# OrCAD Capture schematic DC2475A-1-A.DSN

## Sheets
1 PAGE2: size Custom
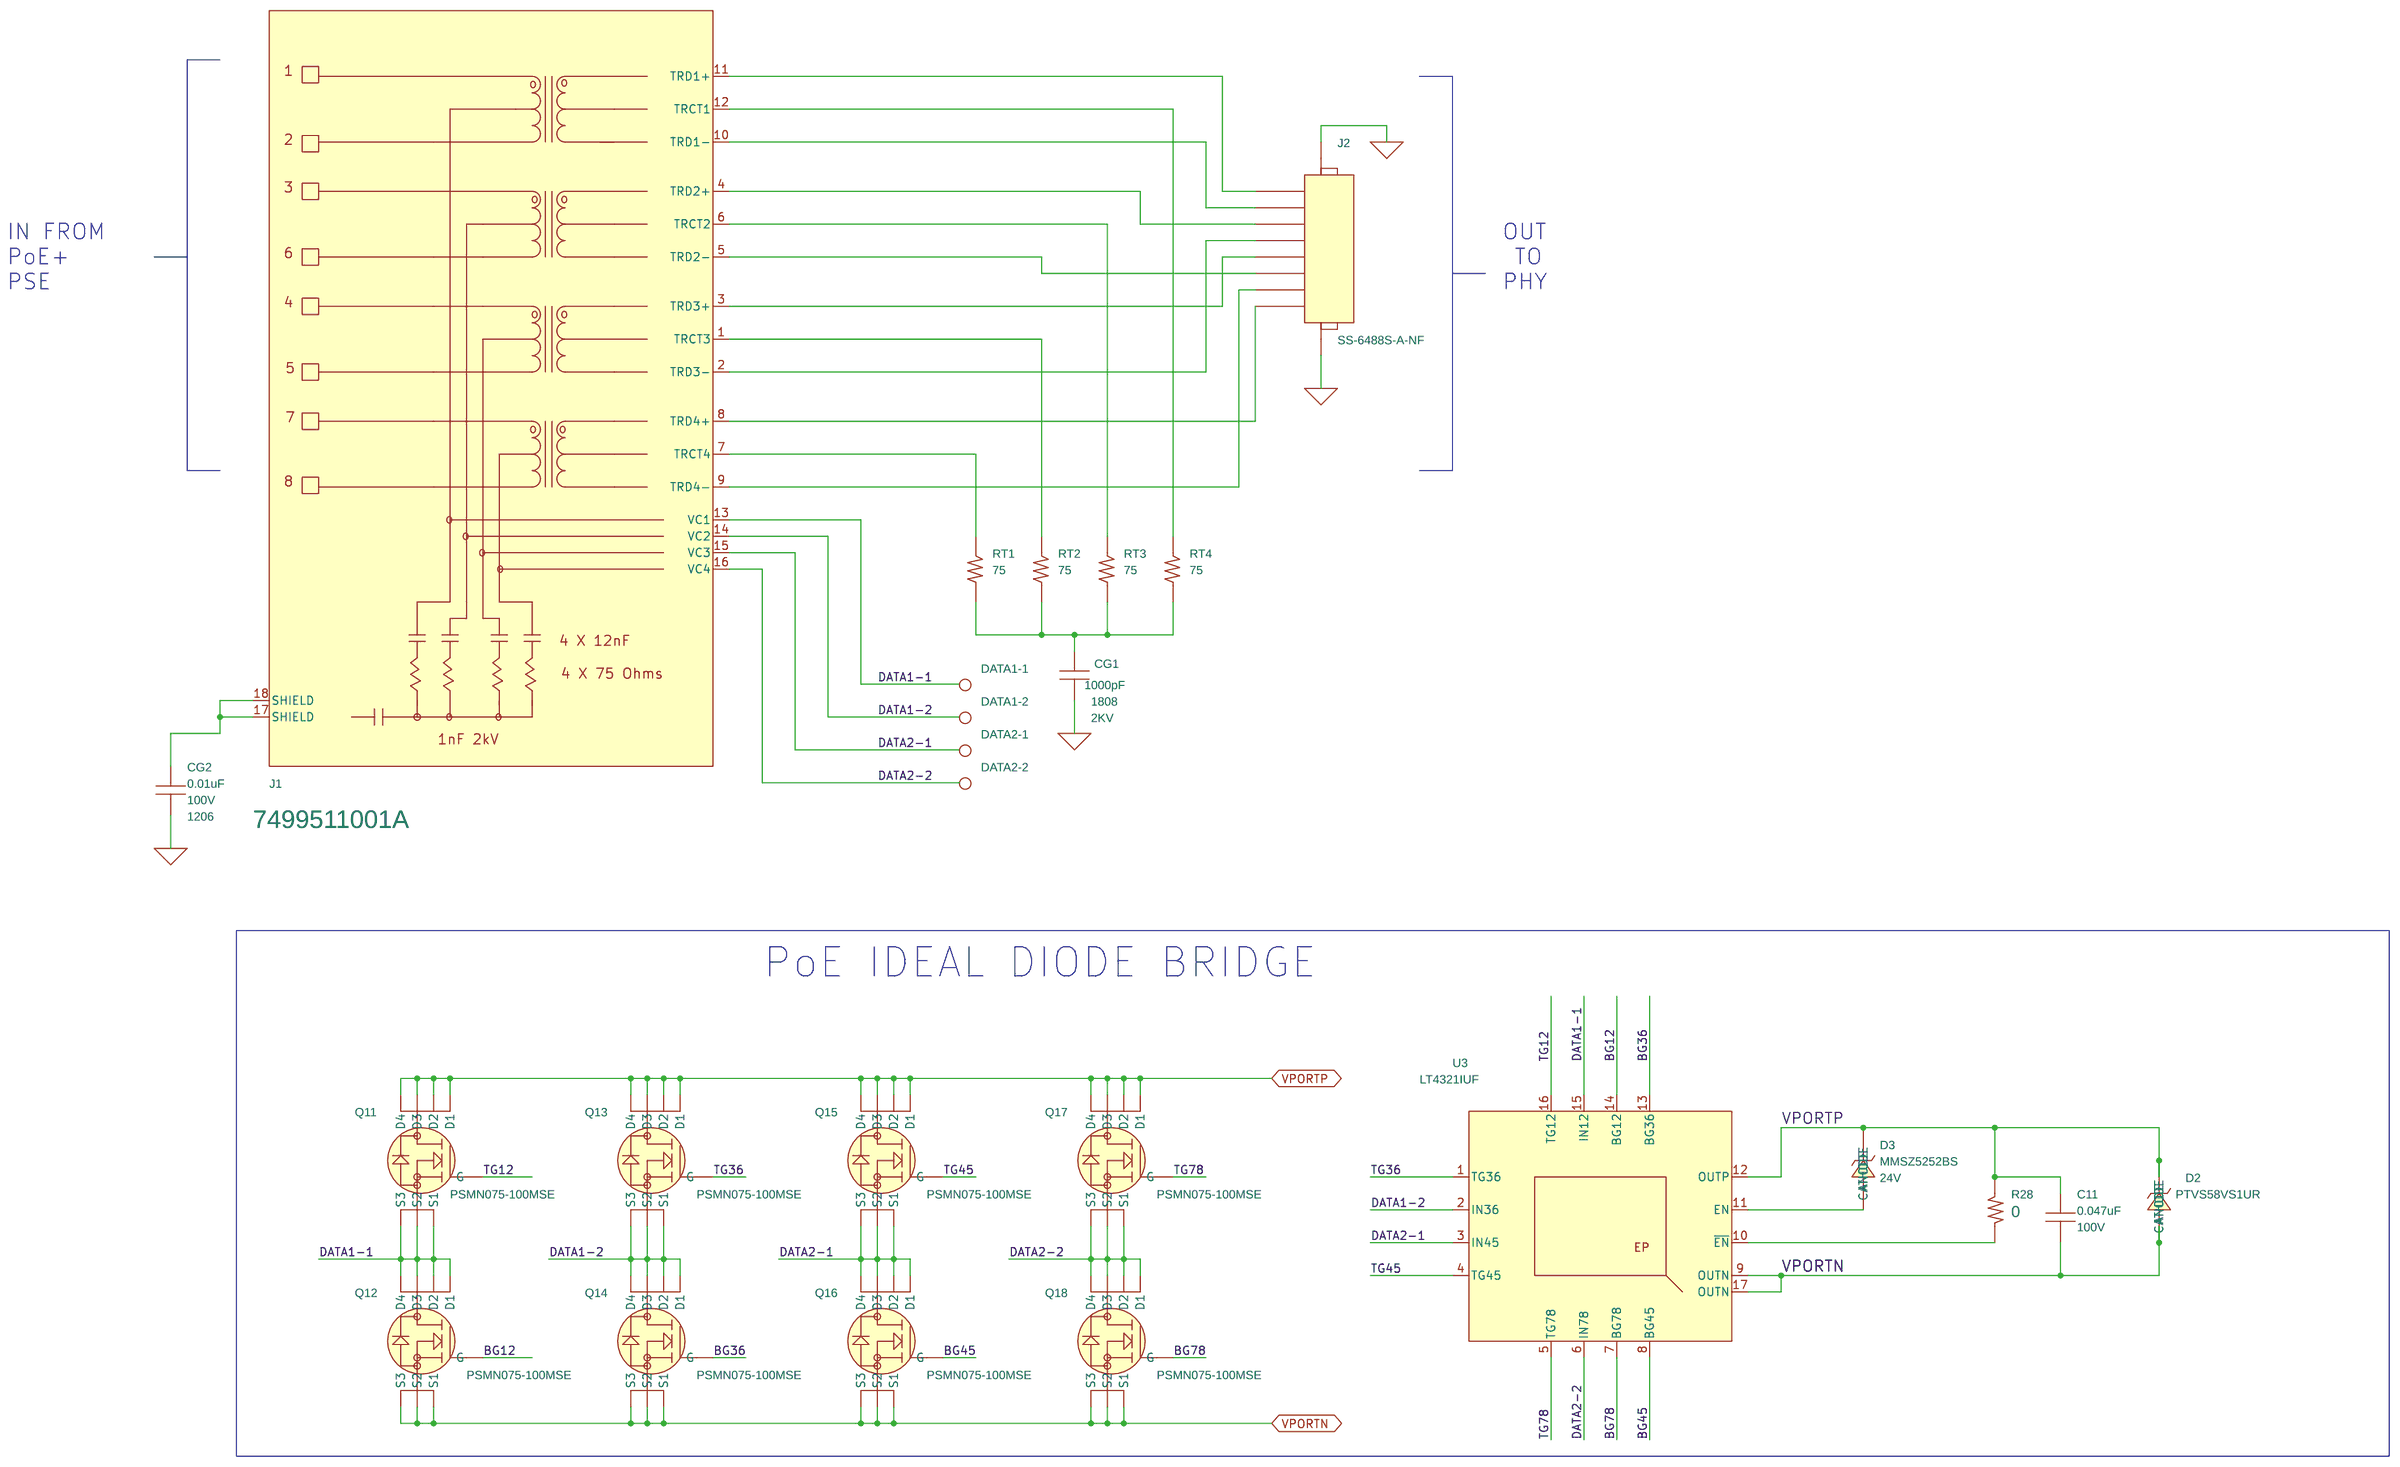
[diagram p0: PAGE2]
2 PAGE1: size Custom
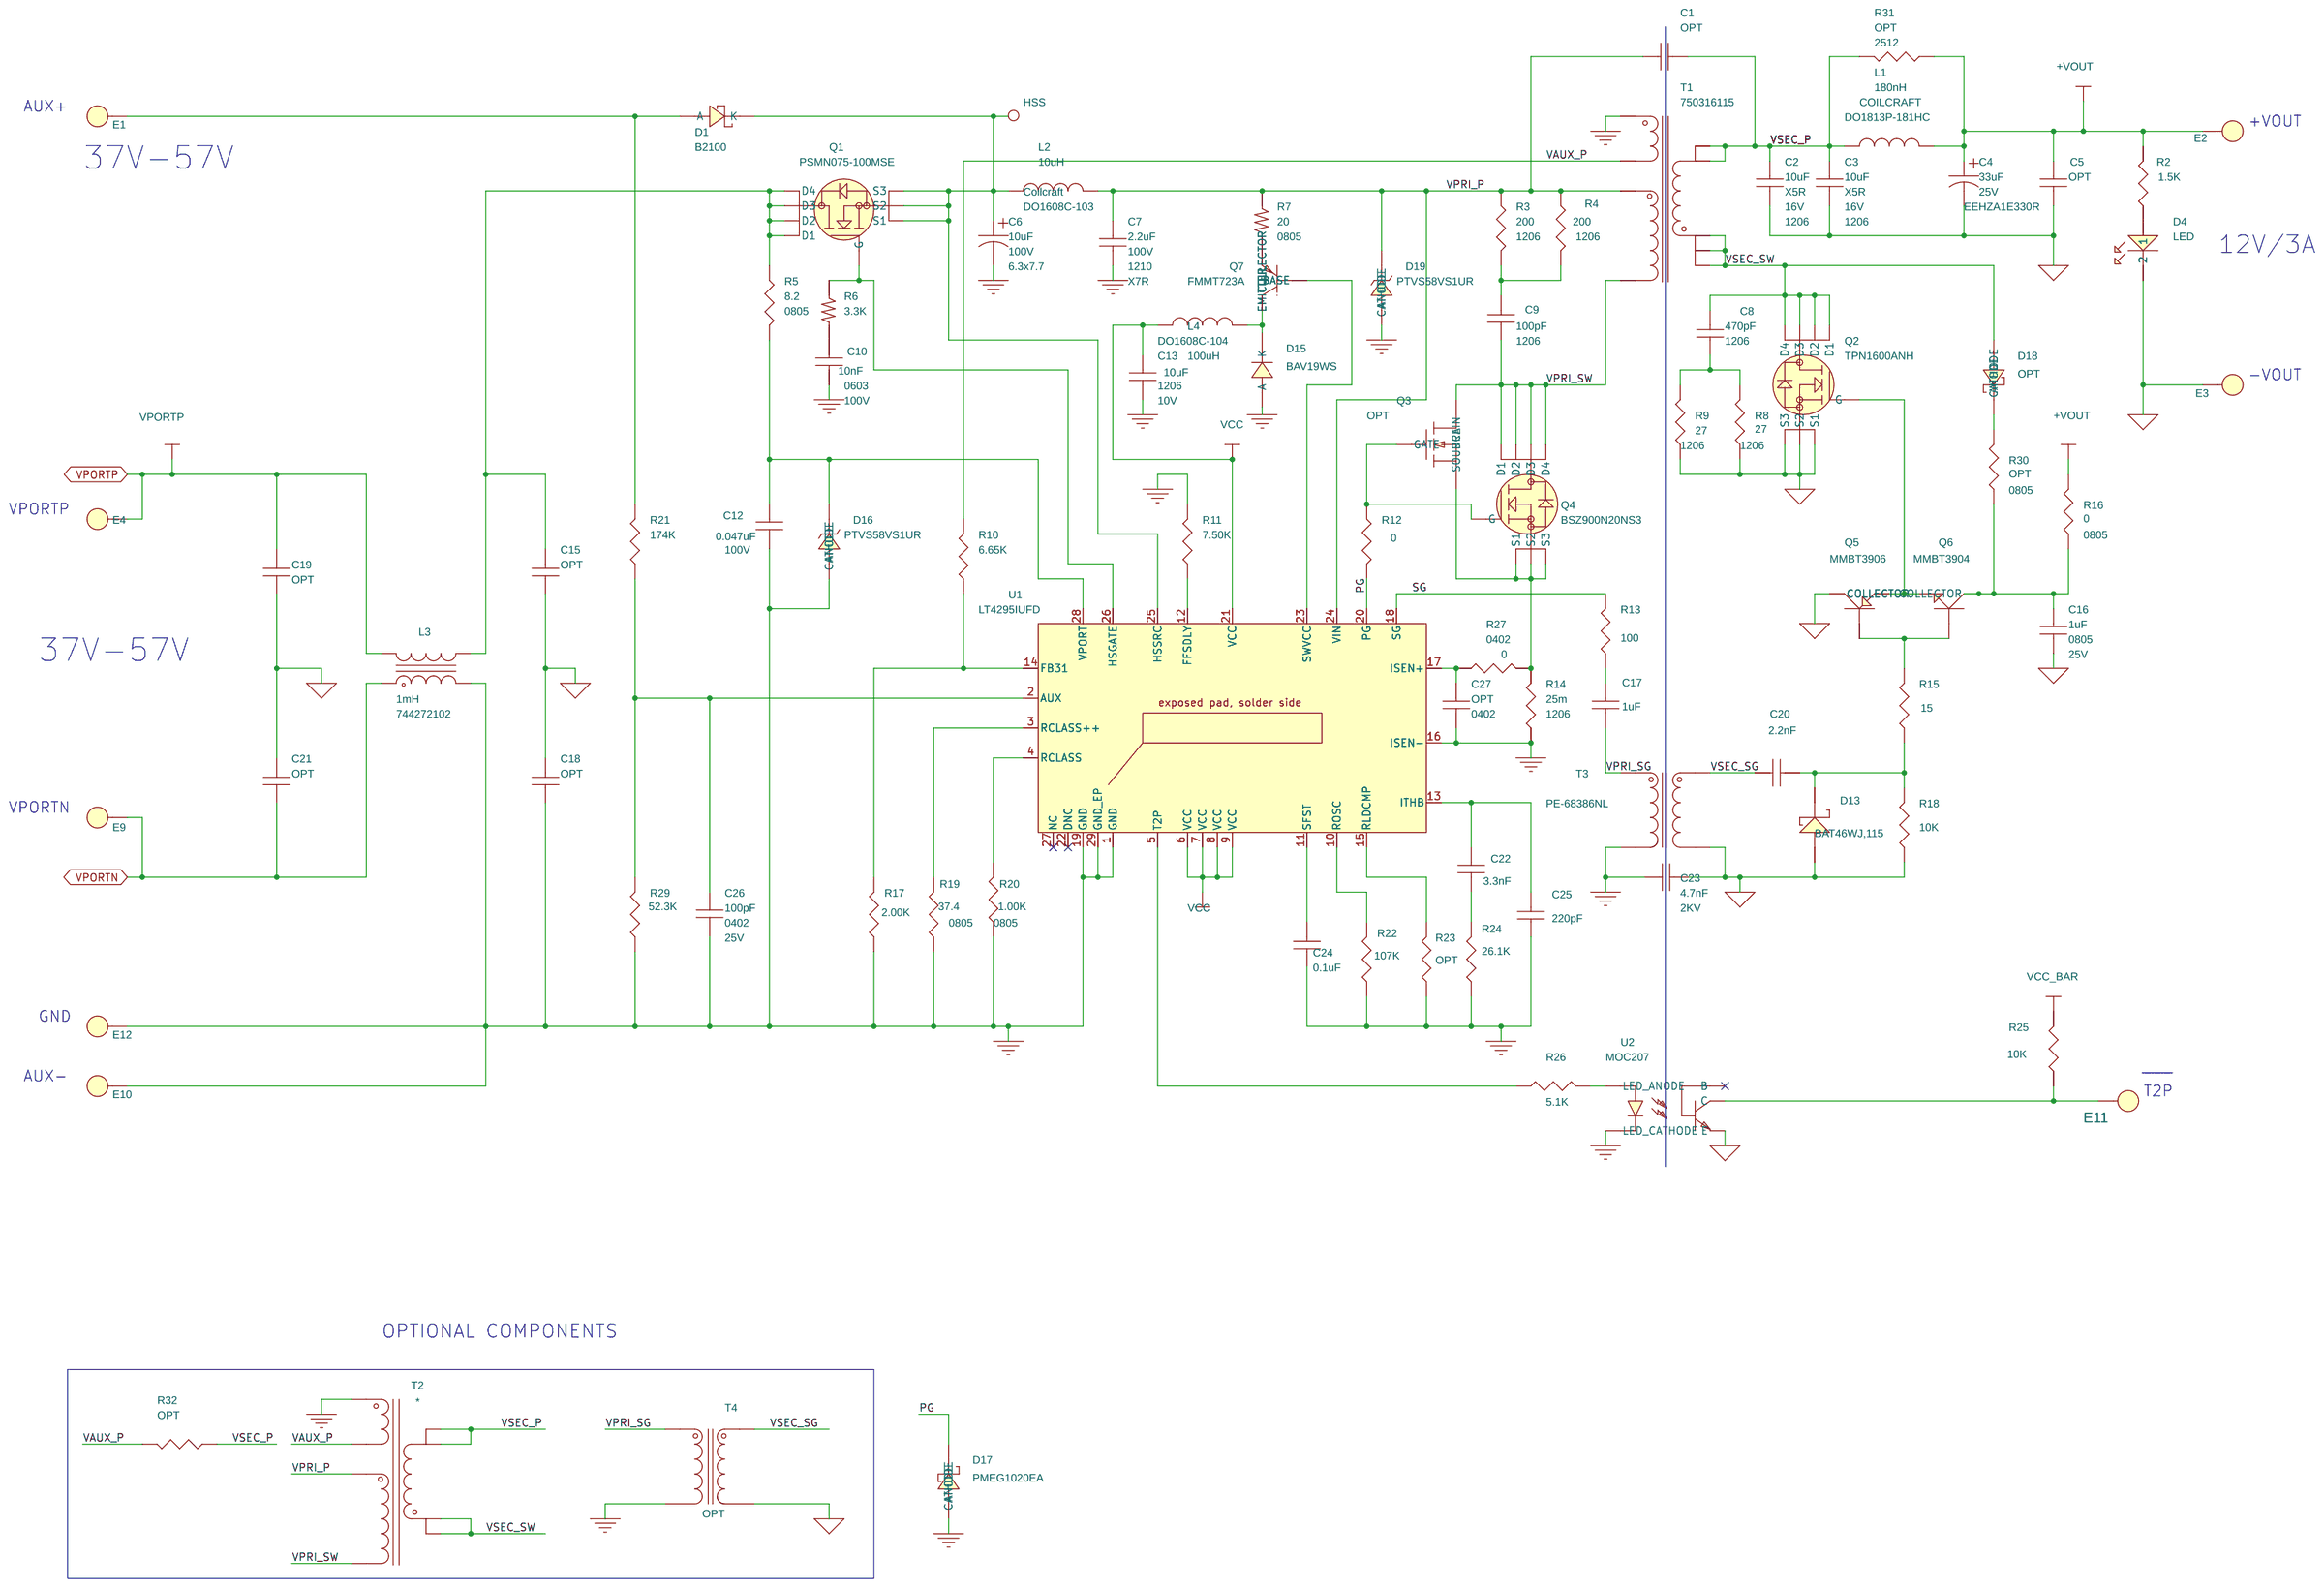
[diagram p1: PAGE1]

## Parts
sheet PAGE1
C1  OPT  [1812]
C2  10uF  [1206]
C3  10uF  [1206]
C4  33uF  [C-SANYO-B6-5.0X5.9]
C5  OPT  [1210]
C6  10uF  [SANYO\6.3X7.7]
C7  2.2uF  [1210]
C8  470pF  [1206]
C9  100pF  [1206]
C10  10nF  [0603]
C12  0.047uF  [0805]
C13  10uF  [1206]
C15  OPT  [1812]
C16  1uF  [0805]
C17  1uF  [0603]
C18  OPT  [1812]
C19  OPT  [1812]
C20  2.2nF  [0603]
C21  OPT  [1812]
C22  3.3nF  [0603]
C23  4.7nF  [1812]
C24  0.1uF  [0603]
C25  220pF  [0603]
C26  100pF  [0402]
C27  OPT  [0402]
D1  B2100  [SMB-DIODE]
D4  LED  [LED-ROHM-SML-010]
D13  BAT46WJ,115  [SOD323]
D15  BAV19WS
D16  PTVS58VS1UR  [SOD123]
D17  PMEG1020EA  [SOD323]
D18  OPT  [SOD323]
D19  PTVS58VS1UR  [SOD123]
E1  PAD150-094  [PAD150-094]
E2  PAD150-094  [PAD150-094]
E3  PAD150-094  [PAD150-094]
E4  PAD150-094  [PAD150-094]
E9  PAD150-094  [PAD150-094]
E10  PAD150-094  [PAD150-094]
E11  PAD150-094  [PAD150-094]
E12  PAD150-094  [PAD150-094]
HSS  E-SMT-060  [SMTP]
L1  180nH  [DO1813P-HC]
L2  10uH  [IND-COILCRAFT-DO1608C]
L3  1mH  [IND-WURTH-744272332]
L4  100uH  [IND-COILCRAFT-DO1608C]
Q1  PSMN075-100MSE  [POWERPAK1212]
Q2  TPN1600ANH  [POWER33]
Q3  OPT  [SOT23]
Q4  BSZ900N20NS3  [POWER33]
Q5  MMBT3906  [SOT23]
Q6  MMBT3904  [SOT23]
Q7  FMMT723A  [SOT23]
R2  1.5K  [0805]
R3  200  [1206]
R4  200  [1206]
R5  8.2  [0805]
R6  3.3K  [0603]
R7  20  [0805]
R8  27  [1206]
R9  27  [1206]
R10  6.65K  [0603]
R11  7.50K  [0603]
R12  0  [0603]
R13  100  [0603]
R14  25m  [1206]
R15  15  [0603]
R16  0  [0805]
R17  2.00K  [0603]
R18  10K  [0603]
R19  37.4  [0805]
R20  1.00K  [0805]
R21  174K  [0603]
R22  107K  [0603]
R23  OPT  [0603]
R24  26.1K  [0603]
R25  10K  [0603]
R26  5.1K  [0603]
R27  0  [0402]
R29  52.3K  [0603]
R30  OPT  [0805]
R31  OPT  [2512]
R32  OPT  [1812]
T1  750316115  [TRANS-PULSE-EP13]
T2  *  [TRANS-WURTH-EP7]
T3  PE-68386NL  [TRANSFORMER/PULSE/PE-68386]
T4  OPT  [TRANS-EPCOS-T5476]
U1  LT4295IUFD  [QFN28UFD-4X5]
U2  MOC207  [SO8NB]
sheet PAGE2
C11  0.047uF  [0603]
CG1  1000pF  [1808]
CG2  0.01uF  [1206]
D2  PTVS58VS1UR  [SOD123]
D3  MMSZ5252BS  [SOD323]
DATA1-1  E-SMT-060  [SMTP]
DATA1-2  E-SMT-060  [SMTP]
DATA2-1  E-SMT-060  [SMTP]
DATA2-2  E-SMT-060  [SMTP]
J1  7499511001A  [TRANS-WURTH-7499511001]
J2  SS-6488S-A-NF  [CON-SS7188]
Q11  PSMN075-100MSE  [POWERPAK1212]
Q12  PSMN075-100MSE  [POWERPAK1212]
Q13  PSMN075-100MSE  [POWERPAK1212]
Q14  PSMN075-100MSE  [POWERPAK1212]
Q15  PSMN075-100MSE  [POWERPAK1212]
Q16  PSMN075-100MSE  [POWERPAK1212]
Q17  PSMN075-100MSE  [POWERPAK1212]
Q18  PSMN075-100MSE  [POWERPAK1212]
R28  0  [0603]
RT1  75  [0603]
RT2  75  [0603]
RT3  75  [0603]
RT4  75  [0603]
U3  LT4321IUF  [QFN16UF-4X4]

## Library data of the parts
C1 = CAP-NP: 1st Part: Cap; 2nd Part Type: Cer; 5th Voltage: 2kV
C2 C3 = CAP-NP: 1st Part: CAP; 2nd Part Type: Cer; 3rd Tempco: X5R; 5th Voltage: 16V; 6th Tolerance: 10%; 8th Mfr: Murata; 9th Part Number: GRM31CR61C106KA88
C4 = CAP: 2nd Part Type: Elec; 5th Voltage: 25V; 6th Tolerance: 20%; 7th Size: 5.0X5.8; 8th Mfr: PANASONIC; 9th Part Number: EEHZA1E330R
C5 = CAP-NP: 1st Part: CAP; 2nd Part Type: Cer; 3rd Tempco: X7U; 5th Voltage: 6.3V; 6th Tolerance: 10%
C6 = CAP: 2nd Part Type: Elec; 5th Voltage: 100V; 6th Tolerance: 10%; 7th Size: 6.3x7.7; 8th Mfr: SunCon; 9th Part Number: 100CE10BS
C7 = CAP-NP: 1st Part: CAP; 2nd Part Type: Cer; 3rd Tempco: X7R; 5th Voltage: 100V; 6th Tolerance: 10%; 8th Mfr: Murata; 9th Part Number: GRM32ER72A225KA35
C8 = CAP-NP: 1st Part: Cap; 2nd Part Type: Cer; 3rd Tempco: U2J; 5th Voltage: 630V; 6th Tolerance: 5%; 8th Mfr: Murata; 9th Part Number: GRM31A7U2J471JW31D
C9 = CAP-NP: 1st Part: Cap; 2nd Part Type: Cer; 3rd Tempco: U2J; 5th Voltage: 630V; 6th Tolerance: 5%; 8th Mfr: Murata
C10 = CAP-NP: 1st Part: Cap; 2nd Part Type: Cer; 3rd Tempco: X7R; 5th Voltage: 100V; 6th Tolerance: 20%; 8th Mfr: TBD
C12 = CAP-NP: 1st Part: Cap; 2nd Part Type: Cer; 3rd Tempco: X7R; 5th Voltage: 100V; 6th Tolerance: 10%; 8th Mfr: TBD
C13 = CAP-NP: 1st Part: Cap; 2nd Part Type: Cer; 3rd Tempco: X7R; 5th Voltage: 10V; 6th Tolerance: 10%; 8th Mfr: Murata; 9th Part Number: GRM31CR71A106KA01L
C15 C18 C19 C21 = CAP-NP: 1st Part: Cap; 2nd Part Type: Cer; 3rd Tempco: X5R; 5th Voltage: 2KV; 6th Tolerance: 20%
C16 C22 = CAP-NP: 1st Part: Cap; 2nd Part Type: Cer; 3rd Tempco: X7R; 5th Voltage: 25V; 6th Tolerance: 10%; 8th Mfr: TBD
C17 = CAP-NP: 1st Part: Cap; 2nd Part Type: Cer; 3rd Tempco: X7R; 5th Voltage: 25V; 6th Tolerance: 10%; 8th Mfr: Murata; 9th Part Number: GRM188R71E105KA12
C20 = CAP-NP: 1st Part: Cap; 2nd Part Type: Cer; 3rd Tempco: X7R; 5th Voltage: 25V; 6th Tolerance: 10%; 8th Mfr: Murata; 9th Part Number: GRM188R71E222KA01
C23 = CAP-NP: 1st Part: Cap; 2nd Part Type: Cer; 3rd Tempco: X7R; 5th Voltage: 2KV; 8th Mfr: Murata; 9th Part Number: GR443DR73D472KW01L
C24 = CAP-NP: 1st Part: Cap; 2nd Part Type: Cer; 3rd Tempco: X7R; 5th Voltage: 25V; 6th Tolerance: 20%; 8th Mfr: TBD
C25 C26 = CAP-NP: 1st Part: Cap; 2nd Part Type: Cer; 3rd Tempco: X7R; 5th Voltage: 25V; 6th Tolerance: 10%; 8th Mfr: TBD; 9th Part Number: TBD
C27 = CAP-NP: 1st Part: Cap; 2nd Part Type: Cer; 3rd Tempco: X7R; 5th Voltage: 6.3V; 6th Tolerance: 10%; 8th Mfr: TBD
D1 = DIODE_SCHOTTKY21_0: 1st Part: DIODE; 2nd Part Type: SCHOTTKY; 5th Voltage: 100; 7th Size: SMB; 8th Mfr: DIODE INC
D4 = LED_0: 1st Part: DIODE; 8th Mfr: ROHM; 9th Part Number: SML-010FTT86L
D13 = DIODE-SCHOTTKY_0: 1st Part: DIODE; 2nd Part Type: Schottky; 5th Voltage: 100; 8th Mfr: NXP
D15 = DIODE_4: 1st Part: Diode; 2nd Part Type: DIODE; 5th Voltage: 120V; 7th Size: SOD323; 8th Mfr: DIODE INC
D16 = DIODE_ZENER_0: 1st Part: DIODE; 2nd Part Type: TVS; 5th Voltage: 60; 8th Mfr: NXP
D17 = DIODE_SCHOTTKY_0: 1st Part: Diode; 2nd Part Type: Schottky; 5th Voltage: 10V; 8th Mfr: NXP
D18 = DIODE_SCHOTTKY_0: 1st Part: Diode; 2nd Part Type: DIODE INC; 5th Voltage: 30V; 8th Mfr: DIODE INC
D2 D19 = DIODE_ZENER_0: 1st Part: DIODE; 2nd Part Type: TVS; 5th Voltage: 58; 8th Mfr: NXP
E1 E4 E9 E10 E12 = E: TURRETS; 1st Part: TP; 2nd Part Type: TURRET; 7th Size: 0.094"; 8th Mfr: MILL-MAX; 9th Part Number: 2501-2-00-80-00-00-07-0; Part Number: MILLMAX 2501-2
E2 E3 E11 = E: 1st Part: TP; 2nd Part Type: TURRET; 7th Size: 0.094"; 8th Mfr: MILL-MAX; 9th Part Number: 2501-2-00-80-00-00-07-0
DATA1-1 DATA1-2 DATA2-1 DATA2-2 HSS = E-SMT-060: 1st Part: CONN; 2nd Part Type: TP
L1 = IND: 8th Mfr: COILCRAFT; 9th Part Number: DO1813P-181HC
L2 = IND: 8th Mfr: Coilcraft; 9th Part Number: DO1608C-103
L3 = IND_0: 1st Part: IND; 2nd Part Type: CMC; 8th Mfr: Wurth; 9th Part Number: 744272102
L4 = IND: 8th Mfr: Coilcraft; 9th Part Number: DO1608C-104
Q1 Q11-Q18 = MOSFET_N-DIODE-A-SO8: 1st Part: MOSFET; 2nd Part Type: N-CH; 5th Voltage: 100; 7th Size: LFPAK33; 8th Mfr: NXP
Q2 = MOSFET_N-DIODE-A-SO8: 1st Part: MOSFET; 2nd Part Type: N-CH; 5th Voltage: 100V; 7th Size: POWER-33; 8th Mfr: TOSHIBA
Q3 = FDN8601_1: 1st Part: MOSFET; 2nd Part Type: N-CH; 5th Voltage: 100
Q4 = MOSFET_N-DIODE-A-SO8: 1st Part: MOSFET; 2nd Part Type: N-CH; 5th Voltage: 150; 7th Size: PG-TDSON-8; 8th Mfr: INFINEON
Q5 = PNP_0: 1st Part: TRANSISTOR; 2nd Part Type: PNP; 5th Voltage: 40; 8th Mfr: FAIRCHILD
Q6 = NPN_0: 1st Part: TRANSISTOR; 2nd Part Type: NPN; 5th Voltage: 40; 8th Mfr: FAIRCHILD
Q7 = MMBT5401L: 1st Part: Tran; 2nd Part Type: PNP; 5th Voltage: 100V; 8th Mfr: DIODES INC; 9th Part Number: FMMT723
R2-R5 R8 R9 R12 R13 R15 R16 R18 R22 R25-R27 = CR18-274JM: 1st Part: Res; 2nd Part Type: Chip; 6th Tolerance: 5%; 8th Mfr: TBD
R6 R7 = R: 1st Part: Res; 2nd Part Type: Chip; 6th Tolerance: 5%; 8th Mfr: TBD
R10 R11 R14 R17 R20 R24 R32 = CR18-274JM: 1st Part: Res; 2nd Part Type: Chip; 6th Tolerance: 1%; 8th Mfr: TBD
R19 = CR18-274JM: 1st Part: Res; 2nd Part Type: Chip; 6th Tolerance: 1%; 8th Mfr: OPT
R21 R29 = CR18-274JM: 1st Part: Res; 2nd Part Type: Chip; 6th Tolerance: 1%; 8th Mfr: TBD; 9th Part Number: TBD
R23 R30 = CR18-274JM: 1st Part: Res; 2nd Part Type: Chip; 6th Tolerance: 5%
R31 = CR18-274JM: 1st Part: Res; 2nd Part Type: Chip; 4th Value: 0; 6th Tolerance: 5%; 8th Mfr: TBD
T1 = TRANS-VP3_1: 1st Part: XFMR; 2nd Part Type: Flyback Tran; 8th Mfr: WURTH
T2 = TRANS-VP3_2: 1st Part: XFMR; 2nd Part Type: Flyback Tran; 8th Mfr: WURTH; 9th Part Number: TBD
T3 = TRANS-PA0297_2: 1st Part: XFMR; 2nd Part Type: SMD GATE DRIVE; 4TH PART FIELD: PULSE,; 8th Mfr: PULSE
T4 = TRANS-PA0297_1: 1st Part: XFMR; 2nd Part Type: SMD GATE DRIVE; 4TH PART FIELD: PULSE,; 8th Mfr: EPCOS; 9th Part Number: T5476
U1 = LT4276_3: 1st Part: IC; 2nd Part Type: PD & Switcher Controller; 7th Size: QFN28; 8th Mfr: Linear Tech
U2 = MOC207: 1st Part: Opto; 5th Voltage: 70V; 7th Size: SO8; 8th Mfr: FAIRCHILD; 9th Part Number: MOC207M
C11 CG2 = CAP-NP: 1st Part: CAP; 2nd Part Type: Cer; 3rd Tempco: X7R; 5th Voltage: 100V; 6th Tolerance: 20%; 8th Mfr: TBD; Voltage Rating: 100V
CG1 = CAP-NP: 1st Part: Cap; 2nd Part Type: Cer; 3rd Tempco: X7R; 5th Voltage: 2KV; 6th Tolerance: 10%; 8th Mfr: Murata; 9th Part Number: GR442QR73D102KW01L
D3 = DIODE_ZENER_0: 1st Part: DIODE; 2nd Part Type: Zener; 5th Voltage: 24V; 8th Mfr: Diodes Inc; 9th Part Number: MMSZ5256BS
J1 = TRNSFMR_165P_8: 1st Part: CONN; 2nd Part Type: Integrated Jack; 8th Mfr: Wurth
J2 = 8_HEADER_1: 1st Part: CONN; 2nd Part Type: RJ45 Jack; 8th Mfr: Stewart Connector
R28 = R: 1st Part: Res; 2nd Part Type: Chip; 6th Tolerance: 5%; 8th Mfr: TBD; Tolerance: 5%
RT1-RT4 = R: 1st Part: Res; 2nd Part Type: Chip; 6th Tolerance: 5%; 8th Mfr: AAC; 9th Part Number: CR16-750JM
U3 = LT4321_QFN_1: 1st Part: IC; 2nd Part Type: PoE Ideal Bridge Controller; 7th Size: QFN16; 8th Mfr: Linear Tech; 9th Part Number: LT4321

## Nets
GND_POWER: C6.2 C7.2 C10.2 C12.2 C13.2 C18.1 C23.1 C24.1 C25.1 C26.2 C27.2 D15.2(A) D16.2(ANODE) D17.2(ANODE) D19.2(ANODE) E10.1(A) E12.1(A) L3.3 R11.2 R14.2 R17.1 R19.1 R20.1 R22.1 R23.1 R24.1 R29.1 T1.2 T2.2 T3.3 T4.3 U1.1(GND) U1.16(ISEN-) U1.19(GND) U1.29(GND_EP) U2.2(LED_CATHODE)
VCC: C13.1 L4.1 U1.6(VCC) U1.7(VCC) U1.8(VCC) U1.9(VCC) U1.21(VCC)
+VOUT: C4.1 C5.1 E2.1(A) L1.2 R2.2 R16.2 R25.2 R31.1
BG12: Q12.4(G) U3.14(BG12)
BG36: Q14.4(G) U3.13(BG36)
BG45: Q16.4(G) U3.8(BG45)
BG78: Q18.4(G) U3.7(BG78)
DATA1-1: DATA1-1.1 J1.13(VC1) Q11.1(S1) Q11.2(S2) Q11.3(S3) Q12.5(D1) Q12.6(D2) Q12.7(D3) Q12.8(D4) U3.15(IN12)
DATA1-2: DATA1-2.1 J1.14(VC2) Q13.1(S1) Q13.2(S2) Q13.3(S3) Q14.5(D1) Q14.6(D2) Q14.7(D3) Q14.8(D4) U3.2(IN36)
DATA2-1: DATA2-1.1 J1.15(VC3) Q15.1(S1) Q15.2(S2) Q15.3(S3) Q16.5(D1) Q16.6(D2) Q16.7(D3) Q16.8(D4) U3.3(IN45)
DATA2-2: DATA2-2.1 J1.16(VC4) Q17.1(S1) Q17.2(S2) Q17.3(S3) Q18.5(D1) Q18.6(D2) Q18.7(D3) Q18.8(D4) U3.6(IN78)
PG: D17.1(CATHODE) R12.2 U1.20(PG)
SEC_GND: C2.2 C3.2 C4.2 C5.2 C15.1 C16.2 C18.2 C19.1 C21.2 C23.2 CG1.2 CG2.2 D4.2 D13.2 E3.1(A) J2.9 J2.10 Q2.1(S1) Q2.2(S2) Q2.3(S3) Q5.3(COLLECTOR) R8.1 R9.1 R18.1 T3.4 T4.4 U2.5(E)
SG: R13.2 U1.18(SG)
TG12: Q11.4(G) U3.16(TG12)
TG36: Q13.4(G) U3.1(TG36)
TG45: Q15.4(G) U3.4(TG45)
TG78: Q17.4(G) U3.5(TG78)
VAUX_P: R10.2 R32.2 T1.1 T2.1
VPORTN: C11.2 C21.1 D2.2(ANODE) E9.1(A) L3.4 Q12.1(S1) Q12.2(S2) Q12.3(S3) Q14.1(S1) Q14.2(S2) Q14.3(S3) Q16.1(S1) Q16.2(S2) Q16.3(S3) Q18.1(S1) Q18.2(S2) Q18.3(S3) U3.9(OUTN) U3.17(OUTN)
VPORTP: C11.1 C19.2 D2.1(CATHODE) D3.1(CATHODE) E4.1(A) L3.1 Q11.5(D1) Q11.6(D2) Q11.7(D3) Q11.8(D4) Q13.5(D1) Q13.6(D2) Q13.7(D3) Q13.8(D4) Q15.5(D1) Q15.6(D2) Q15.7(D3) Q15.8(D4) Q17.5(D1) Q17.6(D2) Q17.7(D3) Q17.8(D4) R28.1 U3.12(OUTP)
VPRI_P: C1.1 C7.1 D19.1(CATHODE) L2.2 R3.2 R4.2 R7.1 T1.5 T2.4 U1.24(VIN)
VPRI_SG: C17.2 T3.1 T4.2
VPRI_SW: C9.1 Q3.3(DRAIN) Q4.5(D1) Q4.6(D2) Q4.7(D3) Q4.8(D4) T1.3 T2.3
VSEC_P: C1.2 C2.1 C3.1 L1.1 R31.2 R32.1 T1.9 T1.10 T2.7 T2.8
VSEC_SG: C20.1 T3.6 T4.1
VSEC_SW: C8.2 D18.2(ANODE) Q2.5(D1) Q2.6(D2) Q2.7(D3) Q2.8(D4) T1.6 T1.7 T1.8 T2.5 T2.6
N16777712: C16.1 Q6.3(COLLECTOR) R16.1 R30.1
N16777767: C15.2 L3.2 Q1.5(D1) Q1.6(D2) Q1.7(D3) Q1.8(D4) R5.1
N16777792: C22.2 R24.2
N16777907: C20.2 D13.1 R15.1 R18.2
N16777983: C9.2 R3.1 R4.1
N16777990: Q5.1 Q6.1 R15.2
N16778156: C6.1 D1.1(K) HSS.1 L2.1 Q1.1(S1) Q1.2(S2) Q1.3(S3) U1.25(HSSRC)
N16778195: C22.1 C25.2 U1.13(ITHB)
N16778197: C8.1 R8.2 R9.2
N16778651: R26.1 U1.5(T2P)
N16778751: Q2.4(G) Q5.2 Q6.2
N16778819: R10.1 R17.2 U1.14(FB31)
N16778917: C17.1 R13.1
N16835353: R11.1 U1.12(FFSDLY)
N16854739: Q1.4(G) R6.1 U1.26(HSGATE)
N16869121: C12.1 D16.1(CATHODE) R5.2 U1.28(VPORT)
N16895058: R19.2 U1.3(RCLASS++)
N16896043: R20.2 U1.4(RCLASS)
N16911319: R23.2 U1.15(RLDCMP)
N16912256: R22.2 U1.10(ROSC)
N16913595: C24.2 U1.11(SFST)
N16940400: E11.1(A) R25.1 U2.6(C)
N16989975: Q3.2(SOURCE) Q4.1(S1) Q4.2(S2) Q4.3(S3) R14.1 R27.2
N17153217: Q3.1(GATE) Q4.4(G) R12.1
N17470232: C27.1 R27.1 U1.17(ISEN+)
N17491181: Q7.1(BASE) U1.23(SWVCC)
N17579701: R26.2 U2.1(LED_ANODE)
N17674405: D15.1(K) L4.2 Q7.3(COLLECTOR)
N17832538: J1.4(TRD2+) J2.3
N17832540: J1.6(TRCT2) RT3.1
N17832548: CG2.1 J1.17(SHIELD) J1.18(SHIELD)
N17832623: CG1.1 RT1.2 RT2.2 RT3.2 RT4.2
N17832635: J1.3(TRD3+) J2.5
N17832687: J1.9(TRD4-) J2.7
N17832689: J1.2(TRD3-) J2.4
N17832691: J1.8(TRD4+) J2.8
N17832695: J1.7(TRCT4) RT1.1
N17832697: J1.1(TRCT3) RT2.1
N17832701: J1.12(TRCT1) RT4.1
N17832723: J1.11(TRD1+) J2.1
N17832729: J1.10(TRD1-) J2.2
N17832735: J1.5(TRD2-) J2.6
N17867250: D3.2(ANODE) U3.11(EN)
N17867273: R28.2 U3.10(~{EN})
N18283175: D18.1(CATHODE) R30.2
N18441272: C26.1 R21.1 R29.2 U1.2(AUX)
N18452098: D1.2(A) E1.1(A) R21.2
N18683587: D4.1 R2.1
N18683589: Q7.2(EMITTER) R7.2
N18683590: C10.1 R6.2

Not connected (* = marked no-connect by the designer): U1 22(DNC)* 27(NC)*; U2 7(B)*

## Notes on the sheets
sheet 1
- IN FROM
  PoE+
  PSE
- OUT
   TO
  PHY
- PoE IDEAL DIODE BRIDGE
sheet 2
- AUX+
- +VOUT
- 37V-57V
- 12V/3A
- -VOUT
- VPORTP
- 37V-57V
- VPORTN
- GND
- ___
- AUX-
- T2P
- OPTIONAL COMPONENTS
